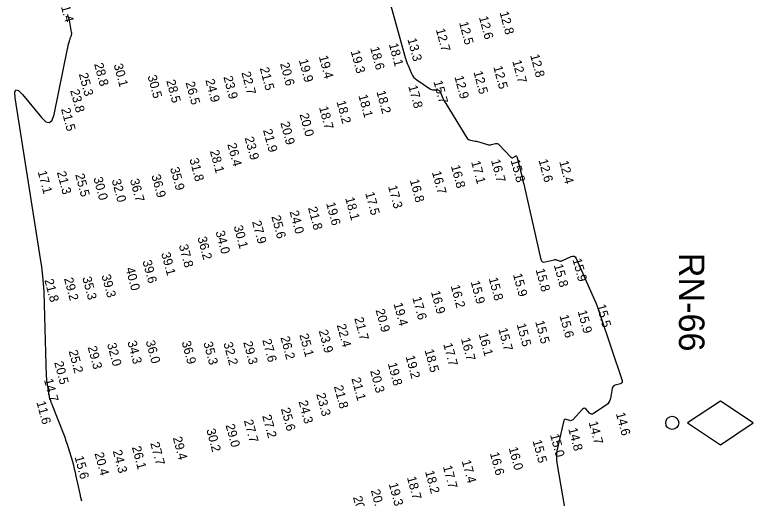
# Model space of a CAD drawing. Extents: x 988130 to 1132882, y 654656 to 841453.
# Drawn here: x 1052367.8 to 1052772.7, y 748838 to 749103.1 of the extents above; entities that cross this region are included whole.
import ezdxf

# ---------------------------------------------------------------- set-up
doc = ezdxf.new("R2010")
doc.units = 0
for name, color, linetype in [('V-CHAN-NAID', 7, 'Continuous'), ('V-TOPO-MAJR', 7, 'Continuous'), ('V-TOPO-SOUN', 7, 'Continuous')]:
    doc.layers.add(name, color=color, linetype=linetype)

msp = doc.modelspace()

# ---------------------------------------------------------------- linework, layer by layer
at = {"layer": 'V-CHAN-NAID'}
msp.add_lwpolyline([(1052736.7, 748879.3), (1052754.7, 748867.3), (1052772.7, 748879.3), (1052754.7, 748891.3)], close=True, dxfattribs=at)
msp.add_circle((1052728.3, 748879.3), 3.6, dxfattribs=at)
at = {"layer": 'V-TOPO-MAJR'}
for points in [[(1052573.8, 749108.65), (1052581.84, 749079.7), (1052582.18, 749078.56), (1052582.55, 749077.43), (1052582.97, 749076.32), (1052583.42, 749075.22), (1052585.31, 749070.84), (1052585.85, 749069.8), (1052586.51, 749068.86), (1052587.31, 749068.03), (1052588.23, 749067.31), (1052595.26, 749062.57), (1052595.73, 749062.3), (1052596.23, 749062.1), (1052596.75, 749061.97), (1052597.3, 749061.92), (1052599.53, 749061.86), (1052600.05, 749061.79), (1052600.48, 749061.59), (1052600.82, 749061.26), (1052601.09, 749060.81), (1052602.57, 749057.33), (1052602.91, 749056.59), (1052603.27, 749055.86), (1052603.66, 749055.15), (1052604.08, 749054.44), (1052615.74, 749035.57), (1052616.12, 749035.07), (1052616.58, 749034.69), (1052617.11, 749034.41), (1052617.72, 749034.25), (1052620.31, 749033.83), (1052620.95, 749033.71), (1052621.59, 749033.57), (1052622.22, 749033.41), (1052622.85, 749033.22), (1052626.94, 749031.91), (1052627.49, 749031.78), (1052628.03, 749031.72), (1052628.58, 749031.74), (1052629.13, 749031.85), (1052631.33, 749032.42), (1052631.86, 749032.49), (1052632.35, 749032.43), (1052632.8, 749032.22), (1052633.21, 749031.88), (1052639.84, 749024.94), (1052640.11, 749024.73), (1052640.39, 749024.64), (1052640.68, 749024.66), (1052640.99, 749024.8), (1052642.26, 749025.61), (1052642.55, 749025.74), (1052642.78, 749025.73), (1052642.96, 749025.58), (1052643.08, 749025.29), (1052645.59, 749015.51), (1052646.03, 749013.75), (1052646.46, 749012), (1052646.88, 749010.24), (1052647.29, 749008.48), (1052656.32, 748968.94), (1052656.63, 748968.15), (1052657.11, 748967.65), (1052657.78, 748967.44), (1052658.63, 748967.53), (1052663.52, 748968.74), (1052663.88, 748968.81), (1052664.24, 748968.81), (1052664.59, 748968.76), (1052664.94, 748968.66), (1052666.34, 748968.14), (1052666.69, 748968.05), (1052667.04, 748968.02), (1052667.38, 748968.07), (1052667.72, 748968.19), (1052672.8, 748970.52), (1052673.69, 748970.78), (1052674.45, 748970.7), (1052675.08, 748970.26), (1052675.58, 748969.47), (1052683.56, 748951.74), (1052684.99, 748948.44), (1052686.34, 748945.12), (1052687.6, 748941.76), (1052688.78, 748938.37), (1052700.77, 748902.53), (1052700.88, 748901.91), (1052700.76, 748901.41), (1052700.42, 748901.02), (1052699.84, 748900.76), (1052697.07, 748899.94), (1052696.45, 748899.68), (1052695.97, 748899.28), (1052695.62, 748898.76), (1052695.42, 748898.12), (1052694.38, 748892.7), (1052694.06, 748891.62), (1052693.57, 748890.66), (1052692.89, 748889.83), (1052692.02, 748889.11), (1052685.1, 748884.37), (1052684.52, 748884.08), (1052683.98, 748884.03), (1052683.46, 748884.21), (1052682.96, 748884.62), (1052681.05, 748886.75), (1052680.57, 748887.15), (1052680.09, 748887.29), (1052679.6, 748887.16), (1052679.12, 748886.77), (1052673.75, 748881.04), (1052673.38, 748880.72), (1052672.97, 748880.55), (1052672.53, 748880.5), (1052672.05, 748880.6), (1052670.06, 748881.24), (1052669.61, 748881.32), (1052669.25, 748881.23), (1052668.99, 748880.97), (1052668.82, 748880.55), (1052665.5, 748866.45), (1052665.03, 748863.93), (1052664.83, 748861.39), (1052664.88, 748858.86), (1052665.2, 748856.31), (1052672.03, 748817.05)], [(1052404.64, 748836.3), (1052404.09, 748838.39), (1052403.6, 748840.49), (1052401.53, 748850.13), (1052401.09, 748852.08), (1052400.61, 748854.02), (1052400.09, 748855.95), (1052399.54, 748857.87), (1052397.23, 748865.54), (1052396.64, 748867.45), (1052396, 748869.34), (1052395.34, 748871.23), (1052394.63, 748873.1), (1052388.49, 748888.91), (1052388.37, 748889.22), (1052388.25, 748889.54), (1052388.13, 748889.85), (1052388.01, 748890.16), (1052387.3, 748891.97), (1052387.29, 748892), (1052387.27, 748892.02), (1052387.25, 748892.04), (1052387.23, 748892.06), (1052387.13, 748892.12), (1052387.11, 748892.14), (1052387.09, 748892.16), (1052387.08, 748892.18), (1052387.07, 748892.21), (1052386.87, 748893.52), (1052386.83, 748893.74), (1052386.8, 748893.97), (1052386.76, 748894.2), (1052386.72, 748894.42), (1052385.69, 748900.46), (1052385.53, 748901.54), (1052385.4, 748902.63), (1052385.31, 748903.72), (1052385.26, 748904.81), (1052384.15, 748944.17), (1052383.84, 748951.08), (1052383.31, 748957.98), (1052382.56, 748964.85), (1052381.59, 748971.7), (1052368.02, 749057.5), (1052367.79, 749060.65), (1052368.37, 749061.99), (1052369.77, 749061.54), (1052371.98, 749059.29), (1052382.44, 749046.7), (1052384.83, 749044.45), (1052386.77, 749043.98), (1052388.27, 749045.31), (1052389.31, 749048.42), (1052396.69, 749084.46), (1052396.8, 749084.95), (1052396.91, 749085.44), (1052397.03, 749085.93), (1052397.15, 749086.42), (1052397.71, 749088.5), (1052397.83, 749088.91), (1052397.95, 749089.32), (1052398.09, 749089.73), (1052398.23, 749090.14), (1052398.81, 749091.76), (1052398.93, 749092.17), (1052399, 749092.59), (1052399, 749093), (1052398.95, 749093.43), (1052397.93, 749099.02), (1052397.72, 749100.09), (1052397.46, 749101.15), (1052397.16, 749102.19), (1052396.81, 749103.23)]]:
    msp.add_lwpolyline(points, dxfattribs=at)

# ---------------------------------------------------------------- texts
at = {"layer": 'V-CHAN-NAID'}
msp.add_text('RN-66', height=14, rotation=270, dxfattribs=at).set_placement((1052731.98, 748972.57))
at = {"layer": 'V-TOPO-SOUN'}
for s, p in [('11.4 ', (1052392.13, 749111.1)), ('12.6 ', (1052622.27, 749101.71)), ('12.8 ', (1052633.57, 749104.32)), ('12.5 ', (1052611.37, 749098.75)), ('12.7 ', (1052598.63, 749094.97)), ('13.3 ', (1052583.06, 749089.66)), ('18.1 ', (1052572.89, 749086.88)), ('19.3 ', (1052551.95, 749083.03)), ('18.6 ', (1052562.6, 749084.97)), ('19.9 ', (1052523.49, 749078.18)), ('19.4 ', (1052534.47, 749080.14)), ('12.7 ', (1052640.55, 749077.64)), ('12.8 ', (1052650.37, 749080.84)), ('28.8 ', (1052411.26, 749076.04)), ('30.1 ', (1052421.97, 749075.63)), ('21.5 ', (1052502.11, 749073.71)), ('20.6 ', (1052513.22, 749076.22)), ('12.5 ', (1052630.15, 749074.48)), ('25.3 ', (1052402.88, 749070.56)), ('30.5 ', (1052440.56, 749069.38)), ('23.9 ', (1052482.15, 749068.93)), ('22.7 ', (1052492.04, 749071.31)), ('12.5 ', (1052619.28, 749071.66)), ('28.5 ', (1052450.82, 749066.85)), ('26.5 ', (1052461.43, 749065.83)), ('24.9 ', (1052472.26, 749067.22)), ('15.7 ', (1052597.32, 749066.45)), ('12.9 ', (1052608.83, 749069.06)), ('23.8 ', (1052398.14, 749061.55)), ('17.8 ', (1052583.52, 749063.87)), ('18.1 ', (1052556.18, 749058.77)), ('18.2 ', (1052566.06, 749060.89)), ('18.2 ', (1052544.16, 749055.41)), ('21.5 ', (1052393.13, 749051.39)), ('18.7 ', (1052534.57, 749052.31)), ('20.0 ', (1052523.91, 749048.43)), ('20.9 ', (1052513.39, 749043.85)), ('21.9 ', (1052503.87, 749039.81)), ('23.9 ', (1052493.8, 749035.58)), ('26.4 ', (1052484.3, 749032.06)), ('28.1 ', (1052474.74, 749028.31)), ('31.8 ', (1052463.54, 749023.83)), ('17.1 ', (1052617.99, 749022.4)), ('16.7 ', (1052628.9, 749023.23)), ('15.8 ', (1052639.64, 749023.25)), ('12.6 ', (1052654.94, 749023.34)), ('12.4 ', (1052666.3, 749022.5)), ('17.1 ', (1052380.29, 749017.01)), ('21.3 ', (1052390.84, 749016.69)), ('35.9 ', (1052452.95, 749018.9)), ('16.7 ', (1052596.49, 749016.76)), ('16.8 ', (1052606.9, 749020.1)), ('25.5 ', (1052400.89, 749015.37)), ('30.0 ', (1052410.87, 749013.5)), ('32.0 ', (1052420.89, 749012.38)), ('36.7 ', (1052430.89, 749012.5)), ('36.9 ', (1052442.67, 749014.9)), ('17.3 ', (1052572.44, 749008.93)), ('16.8 ', (1052584.38, 749012.31)), ('17.5 ', (1052559.91, 749005.3)), ('18.1 ', (1052548.94, 749002.48)), ('21.8 ', (1052528.54, 748997.16)), ('19.6 ', (1052538.48, 748999.67)), ('25.6 ', (1052508.46, 748992.46)), ('24.0 ', (1052518.43, 748995.08)), ('27.9 ', (1052497.84, 748989.59)), ('34.0 ', (1052477.84, 748984.05)), ('30.1 ', (1052487.76, 748987.01)), ('36.2 ', (1052467.93, 748980.81)), ('37.8 ', (1052457.72, 748976.58)), ('39.1 ', (1052448.04, 748972.22)), ('39.6 ', (1052437.77, 748967.94)), ('15.9 ', (1052673.56, 748968.88)), ('15.8 ', (1052663.32, 748965.81)), ('39.3 ', (1052415.31, 748960.12)), ('40.0 ', (1052428.49, 748963.94)), ('15.9 ', (1052640.92, 748960.66)), ('15.8 ', (1052653.33, 748963.33)), ('21.8 ', (1052383.99, 748957.63)), ('29.2 ', (1052394.74, 748958.38)), ('35.3 ', (1052404.76, 748958.89)), ('15.9 ', (1052617.71, 748956.62)), ('15.8 ', (1052627.62, 748958.48)), ('16.2 ', (1052606.77, 748954.37)), ('17.6 ', (1052585.73, 748947.9)), ('16.9 ', (1052595.94, 748951.16)), ('19.4 ', (1052575.43, 748944.6)), ('15.5 ', (1052686.79, 748943.75)), ('20.9 ', (1052565.6, 748941.16)), ('15.9 ', (1052676.4, 748940.49)), ('21.7 ', (1052553.92, 748936.64)), ('15.6 ', (1052666.42, 748938.03)), ('22.4 ', (1052544.31, 748932.92)), ('15.5 ', (1052642.97, 748933.25)), ('15.5 ', (1052653.1, 748934.8)), ('25.1 ', (1052523.81, 748927.62)), ('23.9 ', (1052534.42, 748929.75)), ('16.1 ', (1052622.1, 748928.01)), ('15.7 ', (1052632.87, 748930.8)), ('34.3 ', (1052429.5, 748923.71)), ('36.0 ', (1052439.56, 748923.97)), ('36.9 ', (1052459.25, 748923.61)), ('35.3 ', (1052471.19, 748923.24)), ('29.3 ', (1052493.03, 748923.47)), ('27.6 ', (1052503.47, 748924.71)), ('26.2 ', (1052513.44, 748926.16)), ('16.7 ', (1052612.4, 748925.4)), ('29.3 ', (1052407.72, 748920.85)), ('32.0 ', (1052418.35, 748922.53)), ('32.2 ', (1052482.17, 748922.97)), ('17.7 ', (1052602.7, 748922.5)), ('25.2 ', (1052397.29, 748918.65)), ('19.2 ', (1052582.03, 748915.68)), ('18.5 ', (1052592.45, 748919.14)), ('20.5 ', (1052389.36, 748912.47)), ('19.8 ', (1052572.29, 748911.8)), ('20.3 ', (1052562.59, 748907.86)), ('21.1 ', (1052552.35, 748903.62)), ('14.7 ', (1052383.77, 748902.93)), ('21.8 ', (1052542.73, 748899.26)), ('23.3 ', (1052533.06, 748895.05)), ('24.3 ', (1052523.37, 748890.97)), ('11.6 ', (1052379.64, 748890.65)), ('25.6 ', (1052513.71, 748886.97)), ('27.2 ', (1052503.43, 748883.12)), ('14.6 ', (1052697.37, 748884.45)), ('27.7 ', (1052493.37, 748880.53)), ('14.7 ', (1052682.4, 748879.61)), ('30.2 ', (1052472.78, 748875.53)), ('29.0 ', (1052483.34, 748878.08)), ('14.8 ', (1052671.22, 748876.05)), ('29.4 ', (1052454.4, 748871.13)), ('15.0 ', (1052661.29, 748872.68)), ('27.7 ', (1052442.07, 748868.14)), ('15.5 ', (1052651.66, 748869.43)), ('20.4 ', (1052411.48, 748862.56)), ('24.3 ', (1052421.49, 748863.85)), ('26.1 ', (1052431.96, 748865.96)), ('16.6 ', (1052628.28, 748862.67)), ('16.0 ', (1052638.57, 748865.52)), ('15.6 ', (1052400.53, 748860.6)), ('17.7 ', (1052602.5, 748855.38)), ('17.4 ', (1052612.83, 748858.36)), ('18.2 ', (1052592.74, 748852.59)), ('18.7 ', (1052582.8, 748849.34)), ('20.1 ', (1052563.01, 748842.22)), ('19.3 ', (1052572.82, 748845.87)), ('20.8 ', (1052553.2, 748838.52))]:
    msp.add_text(s, height=5, rotation=285, dxfattribs=at).set_placement(p)

doc.saveas('drawing.dxf')
